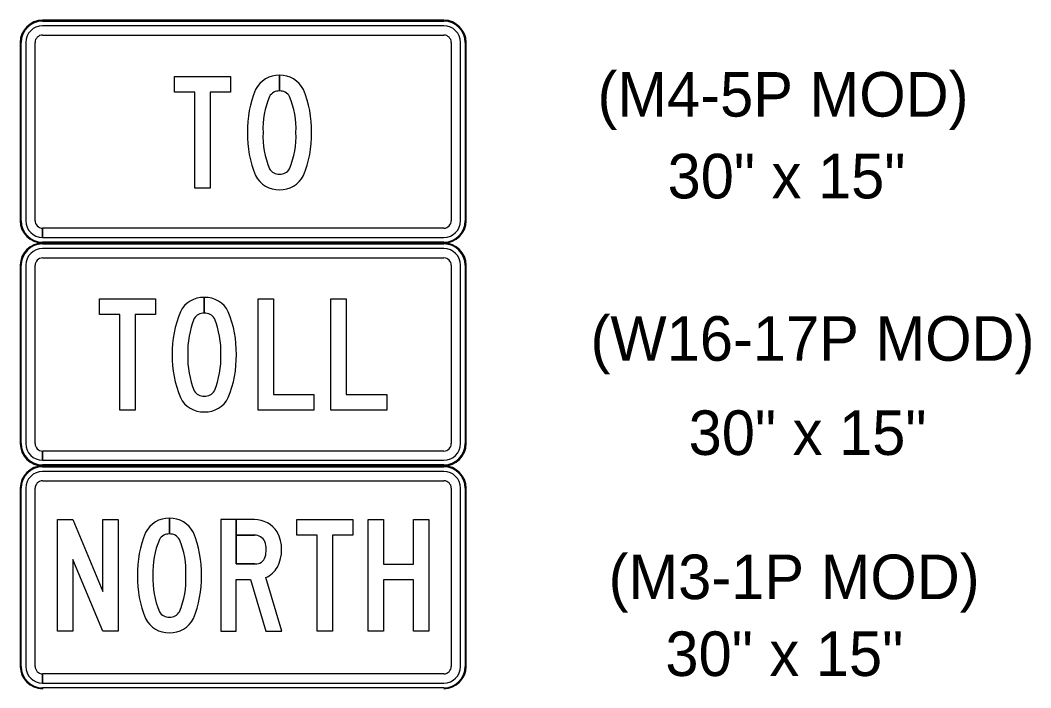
# Model space of a CAD drawing. Extents: x 17890587 to 17890754, y 17897693 to 17897992.
# Drawn here: x 17890612.323 to 17890616.912, y 17897879.973 to 17897883.006 of the extents above; entities that cross this region are included whole.
import ezdxf

# ---------------------------------------------------------------- set-up
doc = ezdxf.new("R2010")
doc.units = 0
for name, color, linetype in [('GSBWFill', 7, 'Continuous'), ('GSColorFill', 7, 'Continuous'), ('GSOutline', 7, 'Continuous'), ('TextMisc', 7, 'Continuous')]:
    doc.layers.add(name, color=color, linetype=linetype)

msp = doc.modelspace()

# ---------------------------------------------------------------- linework, layer by layer
at = {"layer": 'GSBWFill'}
for p, q in [((17890613.5003, 17897882.6844), (17890613.5003, 17897882.7557)), ((17890613.5003, 17897882.7557), (17890613.5003, 17897882.6844))]:
    msp.add_line(p, q, dxfattribs=at)
msp.add_lwpolyline([(17890613.1161, 17897882.6787), (17890613.0239, 17897882.6787), (17890613.0239, 17897882.7496), (17890613.2782, 17897882.7496), (17890613.2782, 17897882.6787), (17890613.1859, 17897882.6787), (17890613.1859, 17897882.2434), (17890613.1161, 17897882.2434)], close=True, dxfattribs=at)
for centre, major_axis, start_param, end_param in [((17890613.4962, 17897882.6365), (0, 0.1193), 6.248265, 7.383959), ((17890613.5044, 17897882.6365), (0, 0.1193), 5.182411, 6.317893), ((17890613.8275, 17897882.5051), (0, 0.48), 1.174158, 1.59042), ((17890613.4976, 17897882.6335), (0, 0.051), 6.22959, 7.30809), ((17890613.503, 17897882.6335), (0, 0.051), 5.258281, 6.336283), ((17890613.173, 17897882.5051), (0, 0.48), 4.692766, 5.109028), ((17890613.7966, 17897882.5127), (0, 0.377), 1.169623, 1.616135), ((17890613.204, 17897882.5127), (0, 0.377), 4.667051, 5.113562), ((17890613.8275, 17897882.4862), (0, 0.48), 1.551173, 1.967435), ((17890613.7966, 17897882.4786), (0, 0.377), 1.525458, 1.97197), ((17890613.204, 17897882.4786), (0, 0.377), 4.311216, 4.757727), ((17890613.173, 17897882.4862), (0, 0.48), 4.31575, 4.732012), ((17890613.4976, 17897882.3578), (0, 0.051), 2.116688, 3.195188), ((17890613.503, 17897882.3578), (0, 0.051), 3.087997, 4.166497), ((17890613.4962, 17897882.3548), (0, 0.1193), 2.040819, 3.176513), ((17890613.5044, 17897882.3548), (0, 0.1193), 3.106673, 4.242367)]:
    msp.add_ellipse(centre, major_axis=major_axis, ratio=0.985, start_param=start_param, end_param=end_param, dxfattribs=at)
at = {"layer": 'GSColorFill'}
for p, q in [((17890614.2465, 17897883.006), (17890612.4241, 17897883.006)), ((17890614.2465, 17897883.006), (17890612.4241, 17897883.006)), ((17890612.4241, 17897883.0018), (17890614.2465, 17897883.0018)), ((17890614.2465, 17897882.9807), (17890612.4241, 17897882.9807)), ((17890612.3229, 17897882.9048), (17890612.3229, 17897882.0949)), ((17890612.3229, 17897882.9048), (17890612.3229, 17897882.0949)), ((17890612.3271, 17897882.0949), (17890612.3271, 17897882.9048)), ((17890612.3482, 17897882.9048), (17890612.3482, 17897882.0949)), ((17890612.3904, 17897882.0949), (17890612.3904, 17897882.9048)), ((17890612.4241, 17897882.9385), (17890614.2465, 17897882.9385)), ((17890614.2802, 17897882.9048), (17890614.2802, 17897882.0949)), ((17890614.3224, 17897882.0949), (17890614.3224, 17897882.9048)), ((17890614.3435, 17897882.9048), (17890614.3435, 17897882.0949)), ((17890614.3477, 17897882.0949), (17890614.3477, 17897882.9048)), ((17890614.3477, 17897882.0949), (17890614.3477, 17897882.9048)), ((17890613.5003, 17897882.6844), (17890613.5003, 17897882.7557)), ((17890613.5003, 17897882.7557), (17890613.5003, 17897882.6844)), ((17890612.4241, 17897882.0189), (17890612.4241, 17897882.0611)), ((17890614.2465, 17897882.0611), (17890612.4246, 17897882.0611)), ((17890612.4246, 17897882.0611), (17890612.4246, 17897882.0189)), ((17890612.4241, 17897881.9936), (17890612.4241, 17897881.9979)), ((17890612.4241, 17897881.9936), (17890614.2465, 17897881.9936)), ((17890614.2465, 17897881.9979), (17890612.4242, 17897881.9979)), ((17890612.4242, 17897881.9979), (17890612.4242, 17897881.9936)), ((17890612.4242, 17897881.9936), (17890614.2465, 17897881.9936)), ((17890614.2465, 17897881.9936), (17890612.4242, 17897881.9936)), ((17890614.2465, 17897881.9936), (17890612.4242, 17897881.9936)), ((17890612.4242, 17897881.9894), (17890614.2465, 17897881.9894)), ((17890612.4246, 17897882.0189), (17890614.2465, 17897882.0189)), ((17890614.2465, 17897881.9683), (17890612.4242, 17897881.9683)), ((17890612.4242, 17897881.9261), (17890614.2465, 17897881.9261)), ((17890612.3229, 17897881.8924), (17890612.3229, 17897881.0825)), ((17890612.3229, 17897881.8924), (17890612.3229, 17897881.0825)), ((17890612.3271, 17897881.0825), (17890612.3271, 17897881.8924)), ((17890612.3482, 17897881.8924), (17890612.3482, 17897881.0825)), ((17890612.3904, 17897881.0825), (17890612.3904, 17897881.8924)), ((17890614.2802, 17897881.8924), (17890614.2802, 17897881.0825)), ((17890614.3224, 17897881.0825), (17890614.3224, 17897881.8924)), ((17890614.3435, 17897881.8924), (17890614.3435, 17897881.0825)), ((17890614.3477, 17897881.0825), (17890614.3477, 17897881.8924)), ((17890614.3477, 17897881.0825), (17890614.3477, 17897881.8924)), ((17890613.1589, 17897881.6754), (17890613.1589, 17897881.7467)), ((17890613.1589, 17897881.7467), (17890613.1589, 17897881.6754)), ((17890612.4242, 17897881.0065), (17890612.4242, 17897881.0487)), ((17890614.2465, 17897881.0487), (17890612.4246, 17897881.0487)), ((17890612.4246, 17897881.0487), (17890612.4246, 17897881.0065)), ((17890612.4242, 17897880.9812), (17890612.4242, 17897880.9855)), ((17890614.2465, 17897880.9855), (17890612.4242, 17897880.9855)), ((17890612.4242, 17897880.9855), (17890612.4242, 17897880.9812)), ((17890614.2465, 17897880.9812), (17890612.4242, 17897880.9812)), ((17890614.2465, 17897880.9812), (17890612.4242, 17897880.9812)), ((17890612.4242, 17897880.9812), (17890614.2465, 17897880.9812)), ((17890612.4242, 17897880.9812), (17890614.2465, 17897880.9812)), ((17890612.4242, 17897880.977), (17890614.2465, 17897880.977)), ((17890612.4246, 17897881.0065), (17890614.2465, 17897881.0065)), ((17890614.2465, 17897880.9559), (17890612.4242, 17897880.9559)), ((17890612.4242, 17897880.9137), (17890614.2465, 17897880.9137)), ((17890612.3229, 17897880.88), (17890612.3229, 17897880.0701)), ((17890612.3229, 17897880.88), (17890612.3229, 17897880.0701)), ((17890612.3272, 17897880.0701), (17890612.3272, 17897880.88)), ((17890612.3483, 17897880.88), (17890612.3483, 17897880.0701)), ((17890612.3904, 17897880.0701), (17890612.3904, 17897880.88)), ((17890614.2803, 17897880.88), (17890614.2803, 17897880.0701)), ((17890614.3224, 17897880.0701), (17890614.3224, 17897880.88)), ((17890614.3435, 17897880.88), (17890614.3435, 17897880.0701)), ((17890614.3477, 17897880.0701), (17890614.3477, 17897880.88)), ((17890614.3477, 17897880.0701), (17890614.3477, 17897880.88)), ((17890613.0005, 17897880.6718), (17890613.0005, 17897880.7431)), ((17890613.0005, 17897880.7431), (17890613.0005, 17897880.6718)), ((17890613.0005, 17897880.6718), (17890613.0005, 17897880.7431)), ((17890613.0005, 17897880.7431), (17890613.0005, 17897880.6718)), ((17890613.5106, 17897880.2307), (17890613.4384, 17897880.4736)), ((17890612.4242, 17897879.9941), (17890612.4242, 17897880.0363)), ((17890614.2465, 17897880.0363), (17890612.4246, 17897880.0363)), ((17890612.4246, 17897880.0363), (17890612.4246, 17897879.9941)), ((17890612.4242, 17897879.9688), (17890612.4242, 17897879.9731)), ((17890614.2465, 17897879.9731), (17890612.4242, 17897879.9731)), ((17890612.4242, 17897879.9731), (17890612.4242, 17897879.9688)), ((17890612.4246, 17897879.9941), (17890614.2465, 17897879.9941))]:
    msp.add_line(p, q, dxfattribs=at)
for points in [[(17890613.1161, 17897882.6787), (17890613.0239, 17897882.6787), (17890613.0239, 17897882.7496), (17890613.2782, 17897882.7496), (17890613.2782, 17897882.6787), (17890613.1859, 17897882.6787), (17890613.1859, 17897882.2434), (17890613.1161, 17897882.2434)], [(17890612.7747, 17897881.6697), (17890612.6825, 17897881.6697), (17890612.6825, 17897881.7405), (17890612.9368, 17897881.7405), (17890612.9368, 17897881.6697), (17890612.8445, 17897881.6697), (17890612.8445, 17897881.2343), (17890612.7747, 17897881.2343)], [(17890613.4027, 17897881.7405), (17890613.4725, 17897881.7405), (17890613.4725, 17897881.3052), (17890613.6569, 17897881.3052), (17890613.6569, 17897881.2343), (17890613.4027, 17897881.2343)], [(17890613.7339, 17897881.7405), (17890613.8037, 17897881.7405), (17890613.8037, 17897881.3052), (17890613.9881, 17897881.3052), (17890613.9881, 17897881.2343), (17890613.7339, 17897881.2343)], [(17890612.5612, 17897880.7369), (17890612.6986, 17897880.4109), (17890612.6986, 17897880.7369), (17890612.7684, 17897880.7369), (17890612.7684, 17897880.2307), (17890612.6986, 17897880.2307), (17890612.5615, 17897880.556), (17890612.5615, 17897880.2307), (17890612.4917, 17897880.2307), (17890612.4917, 17897880.7369)], [(17890612.5612, 17897880.7369), (17890612.6986, 17897880.4109), (17890612.6986, 17897880.7369), (17890612.7684, 17897880.7369), (17890612.7684, 17897880.2307), (17890612.6986, 17897880.2307), (17890612.5615, 17897880.556), (17890612.5615, 17897880.2307), (17890612.4917, 17897880.2307), (17890612.4917, 17897880.7369)], [(17890612.5612, 17897880.7369), (17890612.6986, 17897880.4109), (17890612.6986, 17897880.7369), (17890612.7684, 17897880.7369), (17890612.7684, 17897880.2307), (17890612.6986, 17897880.2307), (17890612.5615, 17897880.556), (17890612.5615, 17897880.2307), (17890612.4917, 17897880.2307), (17890612.4917, 17897880.7369)], [(17890613.6715, 17897880.666), (17890613.5793, 17897880.666), (17890613.5793, 17897880.7369), (17890613.8336, 17897880.7369), (17890613.8336, 17897880.666), (17890613.7413, 17897880.666), (17890613.7413, 17897880.2307), (17890613.6715, 17897880.2307)], [(17890613.6715, 17897880.666), (17890613.5793, 17897880.666), (17890613.5793, 17897880.7369), (17890613.8336, 17897880.7369), (17890613.8336, 17897880.666), (17890613.7413, 17897880.666), (17890613.7413, 17897880.2307), (17890613.6715, 17897880.2307)], [(17890613.6715, 17897880.666), (17890613.5793, 17897880.666), (17890613.5793, 17897880.7369), (17890613.8336, 17897880.7369), (17890613.8336, 17897880.666), (17890613.7413, 17897880.666), (17890613.7413, 17897880.2307), (17890613.6715, 17897880.2307)], [(17890613.9023, 17897880.7369), (17890613.9721, 17897880.7369), (17890613.9721, 17897880.5344), (17890614.1092, 17897880.5344), (17890614.1092, 17897880.7369), (17890614.179, 17897880.7369), (17890614.179, 17897880.2307), (17890614.1092, 17897880.2307), (17890614.1092, 17897880.4636), (17890613.9721, 17897880.4636), (17890613.9721, 17897880.2307), (17890613.9023, 17897880.2307)], [(17890613.9023, 17897880.7369), (17890613.9721, 17897880.7369), (17890613.9721, 17897880.5344), (17890614.1092, 17897880.5344), (17890614.1092, 17897880.7369), (17890614.179, 17897880.7369), (17890614.179, 17897880.2307), (17890614.1092, 17897880.2307), (17890614.1092, 17897880.4636), (17890613.9721, 17897880.4636), (17890613.9721, 17897880.2307), (17890613.9023, 17897880.2307)], [(17890613.9023, 17897880.7369), (17890613.9721, 17897880.7369), (17890613.9721, 17897880.5344), (17890614.1092, 17897880.5344), (17890614.1092, 17897880.7369), (17890614.179, 17897880.7369), (17890614.179, 17897880.2307), (17890614.1092, 17897880.2307), (17890614.1092, 17897880.4636), (17890613.9721, 17897880.4636), (17890613.9721, 17897880.2307), (17890613.9023, 17897880.2307)]]:
    msp.add_lwpolyline(points, close=True, dxfattribs=at)
for points in [[(17890613.3863, 17897880.7369), (17890613.2339, 17897880.7369), (17890613.2339, 17897880.2307), (17890613.3037, 17897880.2307), (17890613.3037, 17897880.4651), (17890613.3681, 17897880.4651), (17890613.4377, 17897880.2307), (17890613.5106, 17897880.2307)], [(17890613.3889, 17897880.536), (17890613.3037, 17897880.536), (17890613.3037, 17897880.7369), (17890613.2339, 17897880.7369), (17890613.2339, 17897880.2307)], [(17890613.3889, 17897880.536), (17890613.3037, 17897880.536), (17890613.3037, 17897880.7369), (17890613.2339, 17897880.7369), (17890613.2339, 17897880.2307)], [(17890613.3863, 17897880.7369), (17890613.3037, 17897880.7369), (17890613.3037, 17897880.666), (17890613.3863, 17897880.666)], [(17890613.3863, 17897880.7369), (17890613.3037, 17897880.7369), (17890613.3037, 17897880.666), (17890613.3863, 17897880.666)], [(17890613.3863, 17897880.666), (17890613.3037, 17897880.666), (17890613.3037, 17897880.536), (17890613.3889, 17897880.536)], [(17890613.2339, 17897880.2307), (17890613.3037, 17897880.2307), (17890613.3037, 17897880.4651), (17890613.3681, 17897880.4651), (17890613.4377, 17897880.2307), (17890613.5106, 17897880.2307), (17890613.4384, 17897880.4736)], [(17890613.2339, 17897880.2307), (17890613.3037, 17897880.2307), (17890613.3037, 17897880.4651), (17890613.3681, 17897880.4651), (17890613.4377, 17897880.2307), (17890613.5106, 17897880.2307), (17890613.4384, 17897880.4736)]]:
    msp.add_lwpolyline(points, dxfattribs=at)
for centre, radius, start, end in [((17890612.4241, 17897882.9048), 0.1012, 90, 180), ((17890612.4241, 17897882.9048), 0.1012, 90, 180), ((17890612.4241, 17897882.9048), 0.097, 90, 180), ((17890614.2465, 17897882.9048), 0.1012, 0, 90), ((17890614.2465, 17897882.9048), 0.1012, 0, 90), ((17890614.2465, 17897882.9048), 0.097, 0, 90), ((17890612.4241, 17897882.9048), 0.0759, 90, 180), ((17890614.2465, 17897882.9048), 0.0759, 0, 90), ((17890612.4241, 17897882.9048), 0.0337, 90, 180), ((17890614.2465, 17897882.9048), 0.0337, 0, 90), ((17890612.4241, 17897882.0949), 0.1012, 180, 270), ((17890612.4241, 17897882.0949), 0.1012, 180, 270), ((17890612.4241, 17897882.0949), 0.097, 180, 270), ((17890612.4241, 17897882.0949), 0.0759, 180, 270), ((17890612.4241, 17897882.0949), 0.0337, 180, 270), ((17890614.2465, 17897882.0949), 0.1012, 270, 0), ((17890614.2465, 17897882.0949), 0.1012, 270, 0), ((17890614.2465, 17897882.0949), 0.097, 270, 0), ((17890614.2465, 17897882.0949), 0.0759, 270, 0), ((17890614.2465, 17897882.0949), 0.0337, 270, 0), ((17890612.4242, 17897881.8924), 0.1012, 90, 180), ((17890612.4242, 17897881.8924), 0.1012, 90, 180), ((17890612.4242, 17897881.8924), 0.097, 90, 180), ((17890614.2465, 17897881.8924), 0.1012, 0, 90), ((17890614.2465, 17897881.8924), 0.1012, 0, 90), ((17890614.2465, 17897881.8924), 0.097, 0, 90), ((17890612.4242, 17897881.8924), 0.0759, 90, 180), ((17890614.2465, 17897881.8924), 0.0759, 0, 90), ((17890612.4242, 17897881.8924), 0.0337, 90, 180), ((17890614.2465, 17897881.8924), 0.0337, 0, 90), ((17890612.4242, 17897881.0825), 0.1012, 180, 270), ((17890612.4242, 17897881.0825), 0.1012, 180, 270), ((17890612.4242, 17897881.0825), 0.097, 180, 270), ((17890612.4242, 17897881.0825), 0.0759, 180, 270), ((17890612.4242, 17897881.0825), 0.0337, 180, 270), ((17890614.2465, 17897881.0825), 0.1012, 270, 0), ((17890614.2465, 17897881.0825), 0.0759, 270, 0), ((17890614.2465, 17897881.0825), 0.0337, 270, 0), ((17890614.2465, 17897881.0825), 0.1012, 270, 0), ((17890614.2465, 17897881.0825), 0.097, 270, 0), ((17890612.4242, 17897880.88), 0.1012, 90, 180), ((17890612.4242, 17897880.88), 0.1012, 90, 180), ((17890612.4242, 17897880.88), 0.097, 90, 180), ((17890614.2465, 17897880.88), 0.1012, 0, 90), ((17890614.2465, 17897880.88), 0.1012, 0, 90), ((17890614.2465, 17897880.88), 0.097, 0, 90), ((17890612.4242, 17897880.88), 0.0759, 90, 180), ((17890614.2465, 17897880.88), 0.0759, 0, 90), ((17890612.4242, 17897880.88), 0.0337, 90, 180), ((17890614.2465, 17897880.88), 0.0337, 0, 90), ((17890612.4242, 17897880.0701), 0.1012, 180, 270), ((17890612.4242, 17897880.0701), 0.1012, 180, 270), ((17890612.4242, 17897880.0701), 0.097, 180, 270), ((17890612.4242, 17897880.0701), 0.0759, 180, 270), ((17890612.4242, 17897880.0701), 0.0337, 180, 270), ((17890614.2465, 17897880.0701), 0.1012, 270, 0), ((17890614.2465, 17897880.0701), 0.1012, 270, 0), ((17890614.2465, 17897880.0701), 0.097, 270, 0), ((17890614.2465, 17897880.0701), 0.0759, 270, 0), ((17890614.2465, 17897880.0701), 0.0337, 270, 0)]:
    msp.add_arc(centre, radius, start, end, dxfattribs=at)
for centre, major_axis, ratio, start_param, end_param in [((17890613.4962, 17897882.6365), (0, 0.1193), 0.985, 6.248265, 7.383959), ((17890613.5044, 17897882.6365), (0, 0.1193), 0.985, 5.182411, 6.317893), ((17890613.8275, 17897882.5051), (0, 0.48), 0.985, 1.174158, 1.59042), ((17890613.4976, 17897882.6335), (0, 0.051), 0.985, 6.22959, 7.30809), ((17890613.503, 17897882.6335), (0, 0.051), 0.985, 5.258281, 6.336283), ((17890613.173, 17897882.5051), (0, 0.48), 0.985, 4.692766, 5.109028), ((17890613.7966, 17897882.5127), (0, 0.377), 0.985, 1.169623, 1.616135), ((17890613.204, 17897882.5127), (0, 0.377), 0.985, 4.667051, 5.113562), ((17890613.8275, 17897882.4862), (0, 0.48), 0.985, 1.551173, 1.967435), ((17890613.7966, 17897882.4786), (0, 0.377), 0.985, 1.525458, 1.97197), ((17890613.204, 17897882.4786), (0, 0.377), 0.985, 4.311216, 4.757727), ((17890613.173, 17897882.4862), (0, 0.48), 0.985, 4.31575, 4.732012), ((17890613.4976, 17897882.3578), (0, 0.051), 0.985, 2.116688, 3.195188), ((17890613.503, 17897882.3578), (0, 0.051), 0.985, 3.087997, 4.166497), ((17890613.4962, 17897882.3548), (0, 0.1193), 0.985, 2.040819, 3.176513), ((17890613.5044, 17897882.3548), (0, 0.1193), 0.985, 3.106673, 4.242367), ((17890613.1548, 17897881.6275), (0, 0.1193), 0.985, 6.248265, 7.383959), ((17890613.163, 17897881.6275), (0, 0.1193), 0.985, 5.182411, 6.317893), ((17890613.4862, 17897881.496), (0, 0.48), 0.985, 1.174158, 1.59042), ((17890613.1562, 17897881.6245), (0, 0.051), 0.985, 6.22959, 7.30809), ((17890613.1616, 17897881.6245), (0, 0.051), 0.985, 5.258281, 6.336283), ((17890612.8316, 17897881.496), (0, 0.48), 0.985, 4.692766, 5.109028), ((17890613.4552, 17897881.5037), (0, 0.377), 0.985, 1.169623, 1.616135), ((17890612.8626, 17897881.5037), (0, 0.377), 0.985, 4.667051, 5.113562), ((17890613.4862, 17897881.4772), (0, 0.48), 0.985, 1.551173, 1.967435), ((17890613.4552, 17897881.4695), (0, 0.377), 0.985, 1.525458, 1.97197), ((17890612.8626, 17897881.4695), (0, 0.377), 0.985, 4.311216, 4.757727), ((17890612.8316, 17897881.4772), (0, 0.48), 0.985, 4.31575, 4.732012), ((17890613.1562, 17897881.3488), (0, 0.051), 0.985, 2.116688, 3.195188), ((17890613.1616, 17897881.3488), (0, 0.051), 0.985, 3.087997, 4.166497), ((17890613.1548, 17897881.3458), (0, 0.1193), 0.985, 2.040819, 3.176513), ((17890613.163, 17897881.3458), (0, 0.1193), 0.985, 3.106673, 4.242367), ((17890612.9964, 17897880.6239), (0, 0.1193), 0.985082, 6.248265, 7.383959), ((17890612.9964, 17897880.6239), (0, 0.1193), 0.985082, 6.248265, 7.383959), ((17890612.9964, 17897880.6239), (0, 0.1193), 0.985082, 6.248265, 7.383959), ((17890613.0046, 17897880.6239), (0, 0.1193), 0.985082, 5.182411, 6.318105), ((17890613.0046, 17897880.6239), (0, 0.1193), 0.985082, 5.182411, 6.317893), ((17890613.0046, 17897880.6239), (0, 0.1193), 0.985082, 5.182411, 6.317893), ((17890613.3887, 17897880.6153), (0, 0.1217), 0.985082, 5.284461, 6.303565), ((17890613.3887, 17897880.6153), (0, 0.1217), 0.985082, 5.284461, 6.303565), ((17890613.3887, 17897880.6153), (0, 0.1217), 0.985082, 5.284461, 6.303565), ((17890613.3278, 17897880.4925), (0, 0.48), 0.985082, 1.174158, 1.59042), ((17890613.3278, 17897880.4925), (0, 0.48), 0.985082, 1.174158, 1.59042), ((17890613.3278, 17897880.4925), (0, 0.48), 0.985082, 1.174158, 1.59042), ((17890612.9978, 17897880.6209), (0, 0.051), 0.985082, 6.22959, 7.30809), ((17890612.9978, 17897880.6209), (0, 0.051), 0.985082, 6.22959, 7.30809), ((17890612.9978, 17897880.6209), (0, 0.051), 0.985082, 6.22959, 7.30809), ((17890613.0032, 17897880.6209), (0, 0.051), 0.985082, 5.258281, 6.33678), ((17890613.0032, 17897880.6209), (0, 0.051), 0.985082, 5.258281, 6.336283), ((17890613.0032, 17897880.6209), (0, 0.051), 0.985082, 5.258281, 6.336283), ((17890612.6732, 17897880.4925), (0, 0.48), 0.985082, 4.692766, 5.109028), ((17890612.6732, 17897880.4925), (0, 0.48), 0.985082, 4.692766, 5.109028), ((17890612.6732, 17897880.4925), (0, 0.48), 0.985082, 4.692766, 5.109028), ((17890613.3881, 17897880.614), (0, 0.0521), 0.985082, 5.168949, 6.317293), ((17890613.3881, 17897880.614), (0, 0.0521), 0.985082, 5.168949, 6.317293), ((17890613.3881, 17897880.614), (0, 0.0521), 0.985082, 5.168949, 6.317293), ((17890613.3437, 17897880.5999), (0, 0.1689), 0.985082, 4.22428, 5.21411), ((17890613.3437, 17897880.5999), (0, 0.1689), 0.985082, 4.22428, 5.21411), ((17890613.3437, 17897880.5999), (0, 0.1689), 0.985082, 4.22428, 5.21411), ((17890613.2968, 17897880.5001), (0, 0.377), 0.985082, 1.169623, 1.616135), ((17890613.2968, 17897880.5001), (0, 0.377), 0.985082, 1.169623, 1.616135), ((17890613.2968, 17897880.5001), (0, 0.377), 0.985082, 1.169623, 1.616135), ((17890612.7042, 17897880.5001), (0, 0.377), 0.985082, 4.667051, 5.113562), ((17890612.7042, 17897880.5001), (0, 0.377), 0.985082, 4.667051, 5.113562), ((17890612.7042, 17897880.5001), (0, 0.377), 0.985082, 4.667051, 5.113562), ((17890613.3108, 17897880.5996), (0, 0.1307), 0.985082, 4.469957, 5.002454), ((17890613.3108, 17897880.5996), (0, 0.1307), 0.985082, 4.469957, 5.002454), ((17890613.3108, 17897880.5996), (0, 0.1307), 0.985082, 4.469957, 5.002454), ((17890613.3927, 17897880.5815), (0, 0.0457), 0.985082, 3.056737, 4.417555), ((17890613.3927, 17897880.5815), (0, 0.0457), 0.985082, 3.056737, 4.417555), ((17890613.3927, 17897880.5815), (0, 0.0457), 0.985082, 3.056737, 4.417555), ((17890613.3893, 17897880.5831), (0, 0.1203), 0.985082, 3.569693, 4.167803), ((17890613.3893, 17897880.5831), (0, 0.1203), 0.985082, 3.569693, 4.167803), ((17890613.3893, 17897880.5831), (0, 0.1203), 0.985082, 3.569693, 4.167803), ((17890613.3278, 17897880.4736), (0, 0.48), 0.985082, 1.551173, 1.967435), ((17890613.3278, 17897880.4736), (0, 0.48), 0.985082, 1.551173, 1.967435), ((17890613.3278, 17897880.4736), (0, 0.48), 0.985082, 1.551173, 1.967435), ((17890613.2968, 17897880.466), (0, 0.377), 0.985082, 1.525458, 1.97197), ((17890613.2968, 17897880.466), (0, 0.377), 0.985082, 1.525458, 1.97197), ((17890613.2968, 17897880.466), (0, 0.377), 0.985082, 1.525458, 1.97197), ((17890612.7042, 17897880.466), (0, 0.377), 0.985082, 4.311216, 4.757727), ((17890612.7042, 17897880.466), (0, 0.377), 0.985082, 4.311216, 4.757727), ((17890612.7042, 17897880.466), (0, 0.377), 0.985082, 4.311216, 4.757727), ((17890612.6732, 17897880.4736), (0, 0.48), 0.985082, 4.31575, 4.732012), ((17890612.6732, 17897880.4736), (0, 0.48), 0.985082, 4.31575, 4.732012), ((17890612.6732, 17897880.4736), (0, 0.48), 0.985082, 4.31575, 4.732012), ((17890612.9964, 17897880.3422), (0, 0.1193), 0.985082, 2.040819, 3.176513), ((17890612.9964, 17897880.3422), (0, 0.1193), 0.985082, 2.040819, 3.176513), ((17890612.9964, 17897880.3422), (0, 0.1193), 0.985082, 2.040819, 3.176513), ((17890612.9978, 17897880.3452), (0, 0.051), 0.985082, 2.116688, 3.195188), ((17890612.9978, 17897880.3452), (0, 0.051), 0.985082, 2.116688, 3.195188), ((17890612.9978, 17897880.3452), (0, 0.051), 0.985082, 2.116688, 3.195188), ((17890613.0032, 17897880.3452), (0, 0.051), 0.985082, 3.087997, 4.166497), ((17890613.0032, 17897880.3452), (0, 0.051), 0.985082, 3.087997, 4.166497), ((17890613.0032, 17897880.3452), (0, 0.051), 0.985082, 3.087997, 4.166497), ((17890613.0046, 17897880.3422), (0, 0.1193), 0.985082, 3.106673, 4.242367), ((17890613.0046, 17897880.3422), (0, 0.1193), 0.985082, 3.106673, 4.242367), ((17890613.0046, 17897880.3422), (0, 0.1193), 0.985082, 3.106673, 4.242367)]:
    msp.add_ellipse(centre, major_axis=major_axis, ratio=ratio, start_param=start_param, end_param=end_param, dxfattribs=at)
at = {"layer": 'GSOutline'}
msp.add_lwpolyline([(17890613.1161, 17897882.6787), (17890613.0239, 17897882.6787), (17890613.0239, 17897882.7496), (17890613.2782, 17897882.7496), (17890613.2782, 17897882.6787), (17890613.1859, 17897882.6787), (17890613.1859, 17897882.2434), (17890613.1161, 17897882.2434)], close=True, dxfattribs=at)
for centre, major_axis, start_param, end_param in [((17890613.4962, 17897882.6365), (0, 0.1193), 6.248265, 7.383959), ((17890613.5044, 17897882.6365), (0, 0.1193), 5.182411, 6.318105), ((17890613.8275, 17897882.5051), (0, 0.48), 1.174158, 1.59042), ((17890613.4976, 17897882.6335), (0, 0.051), 6.22959, 7.30809), ((17890613.503, 17897882.6335), (0, 0.051), 5.258281, 6.33678), ((17890613.173, 17897882.5051), (0, 0.48), 4.692766, 5.109028), ((17890613.7966, 17897882.5127), (0, 0.377), 1.169623, 1.616135), ((17890613.204, 17897882.5127), (0, 0.377), 4.667051, 5.113562), ((17890613.8275, 17897882.4862), (0, 0.48), 1.551173, 1.967435), ((17890613.7966, 17897882.4786), (0, 0.377), 1.525458, 1.97197), ((17890613.204, 17897882.4786), (0, 0.377), 4.311216, 4.757727), ((17890613.173, 17897882.4862), (0, 0.48), 4.31575, 4.732012), ((17890613.4976, 17897882.3578), (0, 0.051), 2.116688, 3.195188), ((17890613.503, 17897882.3578), (0, 0.051), 3.087997, 4.166497), ((17890613.4962, 17897882.3548), (0, 0.1193), 2.040819, 3.176513), ((17890613.5044, 17897882.3548), (0, 0.1193), 3.106673, 4.242367)]:
    msp.add_ellipse(centre, major_axis=major_axis, ratio=0.985, start_param=start_param, end_param=end_param, dxfattribs=at)

# ---------------------------------------------------------------- texts
at = {"layer": 'TextMisc'}
for s, height, p in [('(M4-5P MOD)', 0.202479, (17890614.9443, 17897882.568)), ('30" x 15"', 0.20248, (17890615.2623, 17897882.1965)), ('(W16-17P MOD)', 0.202479, (17890614.9126, 17897881.4588)), ('30" x 15"', 0.20248, (17890615.3579, 17897881.0309)), ('(M3-1P MOD)', 0.202479, (17890614.9947, 17897880.3758)), ('30" x 15"', 0.20248, (17890615.2524, 17897880.0266))]:
    msp.add_text(s, height=height, dxfattribs=at).set_placement(p)

doc.saveas('drawing.dxf')
